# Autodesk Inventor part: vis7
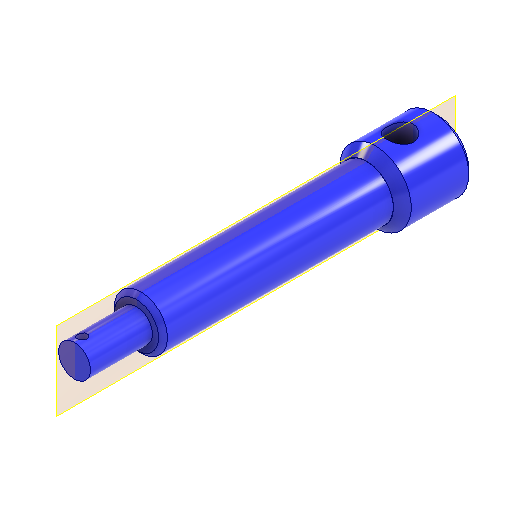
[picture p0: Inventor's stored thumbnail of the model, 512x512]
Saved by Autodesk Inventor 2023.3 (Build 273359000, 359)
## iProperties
Created: 2024-11
Part Number: vis7
Material: Générique
Description: STEP AP203
Document SubType Name: Modeling
Designer: Thier
Density: 1 g/cm^3
Appearance: Bleu - Peinture murale - Brillant
Sending System: SolidWorks 2017
Preprocessor: SwSTEP 2.0
Title: vis7.STEP
Revision Number: ANY
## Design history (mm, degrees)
feature "Enlèv. mat.-Extru.2"
node "Solide1"
